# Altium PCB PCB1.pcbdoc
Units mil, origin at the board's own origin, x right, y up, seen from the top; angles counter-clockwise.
Board outline 3300 x 2640 mil, 2 copper layers (Top Layer, Bottom Layer), stack 62.2 mil thick; 4 components, 6 nets, 17 pads, 1 vias.
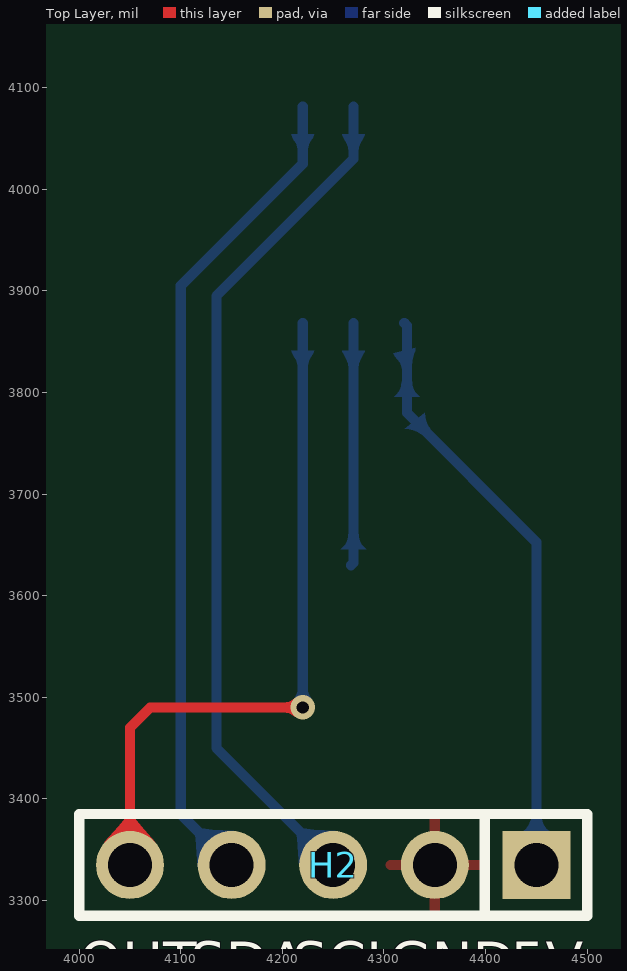
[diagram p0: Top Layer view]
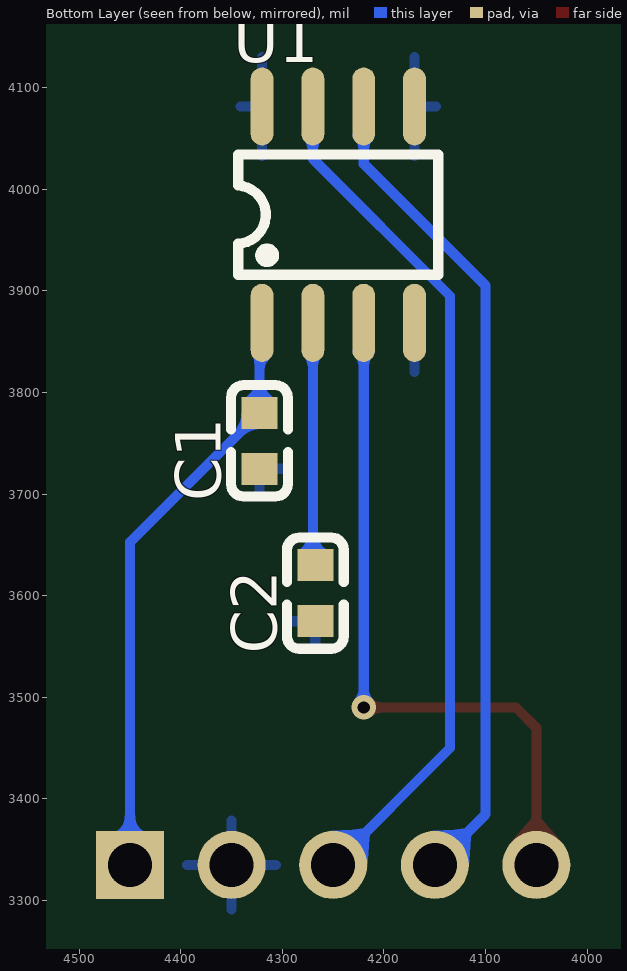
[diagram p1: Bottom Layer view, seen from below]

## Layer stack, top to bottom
Top Solder Mask Layer: solder mask 0.4, Dk 3.3
Top Layer: signal copper 1.4
Dielectric1: surface 59.4, FR4, Dk 4.5
Bottom Layer: signal copper 1.4
Bottom Solder Mask Layer: solder mask 0.4, Dk 3.3

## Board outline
6050,2750 2750,2750 2750,5390 6050,5390

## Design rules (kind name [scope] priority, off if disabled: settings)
BoardOutlineClearance copperThickness1oz [All] p0: genericclearance=10 ignorepadtopadclearanceinfootprint=FALSE except(0: Arc-SplitContinuation Track-SplitContinuation SMDPad-SplitContinuation THPad-SplitContinuation Via-SplitContinuation Fill-SplitContinuation Poly-SplitContinuation Region-SplitContinuation Text-SplitContinuation)
BoardOutlineClearance copperThickness2oz [All] p0: genericclearance=10 ignorepadtopadclearanceinfootprint=FALSE except(0: Arc-SplitContinuation Track-SplitContinuation SMDPad-SplitContinuation THPad-SplitContinuation Via-SplitContinuation Fill-SplitContinuation Poly-SplitContinuation Region-SplitContinuation Text-SplitContinuation)
BoardOutlineClearance otherClearance [All] p0: genericclearance=10 ignorepadtopadclearanceinfootprint=FALSE except(0: Arc-SplitContinuation Track-SplitContinuation SMDPad-SplitContinuation THPad-SplitContinuation Via-SplitContinuation Fill-SplitContinuation Poly-SplitContinuation Region-SplitContinuation Text-SplitContinuation)
Clearance copperThickness1oz [All] p1: gap=7 ignorepadtopadclearanceinfootprint=FALSE
Clearance copperThickness2oz [All] p1: gap=7 ignorepadtopadclearanceinfootprint=FALSE
Clearance otherClearance [All] p1: gap=7 ignorepadtopadclearanceinfootprint=FALSE
DiffPairsRouting differentialPair [All] p1: maxuncoupledlength=10 minlimit=6 maxlimit=Infinity mostfreqgap=6 toplayer_minwidth=5 toplayer_prefwidth=10 toplayer_maxwidth=100 bottomlayer_minwidth=5 bottomlayer_prefwidth=10 bottomlayer_maxwidth=100
PasteMaskExpansion pasteMaskExpansion [All] p1: expansion=0
PlaneConnect innerPlane [All] p1: planeconnectstyle=Relief reliefexpansion=20 reliefentries=4 reliefconductorwidth=10 reliefairgap=10
PolygonConnect copperRegion [All] p1: connectstyle=Relief reliefentries=4 reliefconductorwidth=10 polygonreliefangle="90 Angle" airgapwidth=10
RoutingVias viaSize [All] p1: viastyle="Through Hole" holewidth=12.0078 minholewidth=11.811 maxholewidth=248.0314 width=12.0078 minwidth=11.811 maxwidth=248.0314
SolderMaskExpansion solderMaskExpansion [IsVia] p1: useseparateexpansions=TRUE expansion=-1000 expansionbottom=-1000
SolderMaskExpansion solderMaskExpansion [All] p2: useseparateexpansions=TRUE expansion=2 expansionbottom=2
Width copperThickness1oz [All] p1: maxlimit=100 minlimit=5 preferedwidth=10
Width copperThickness2oz [All] p1: maxlimit=100 minlimit=8 preferedwidth=10

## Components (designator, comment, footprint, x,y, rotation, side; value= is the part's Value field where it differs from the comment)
C1 "100nF" C0603 4322.6,3752.4 r90 bottom
C2 "100nF" C0603 4267.6,3602.4 r90 bottom
H2 "" HDR-TH_5P-P2.54-V-M 4250,3335 r180 top
U1 "AS5600-ASOT" SOIC-8_L5.0-W4.0-P1.27-LS6.0-BL 4245,3975 r180 bottom

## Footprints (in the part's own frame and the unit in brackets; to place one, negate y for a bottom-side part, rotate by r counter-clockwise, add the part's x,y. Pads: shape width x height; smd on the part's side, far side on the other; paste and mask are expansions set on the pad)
C0603 [mil]
  rect 31.5x35.4 smd: 1(-27.5,0) 2(27.6,0)
  silkscreen extent -55,-28 55,28
HDR-TH_5P-P2.54-V-M [mil]
  rect 66.9x66.9 hole 43.3: 1(-200,0)
  round 66.9 hole 43.3: 2(-100,0) 3(0,0) 4(100,0) 5(200,0)
  silkscreen extent -250,-50 250,50
SOIC-8_L5.0-W4.0-P1.27-LS6.0-BL [mil]
  oval 22.4x76.8 smd: 1(-75,-106.5) 2(-25,-106.5) 3(25,-106.5) 4(75,-106.5) 5(75,106.5) 6(25,106.5) 7(-25,106.5) 8(-75,106.5)
  silkscreen extent -98,-59 98,59

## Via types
v1: diameter 24, hole 12, Top Layer to Bottom Layer, 1 vias

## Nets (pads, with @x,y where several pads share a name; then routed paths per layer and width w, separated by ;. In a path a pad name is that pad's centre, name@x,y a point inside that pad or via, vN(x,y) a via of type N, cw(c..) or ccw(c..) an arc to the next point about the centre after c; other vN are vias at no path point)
5V: C1.2 H2.1 U1.1 | length 587.3
  Bottom Layer w10: U1.1 4322.6,3865.9 C1.2 4450,3652.6 H2.1
$1N12: C2.2 U1.2 | length 239.5
  Bottom Layer w10: C2.2 4270,3632.4 U1.2
GND: C1.1 C2.1 H2.2 U1.4 U1.5 U1.8
OUT: H2.5 U1.3 | length 691.8
  Top Layer w10: H2.5 4050,3470 4070,3490 v1(4220,3490)
  Bottom Layer w10: v1(4220,3490) U1.3
SCL: H2.3 U1.7 | length 850.1
  Bottom Layer w10: H2.3 4135,3450 4135,3895 4270,4030 U1.7
SDA: H2.4 U1.6 | length 816.9
  Bottom Layer w10: H2.4 4100,3385 4100,3905 4220,4025 U1.6

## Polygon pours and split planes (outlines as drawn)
GND on Top Layer (solid, remove dead copper, pour order 0): 3065,5080 3065,3030 5485,3030 5485,5080
GND on Bottom Layer (solid, remove dead copper, pour order 2): 3000,5140 3000,3000 5800,3000 5800,5140

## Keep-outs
Board Outline Layer:
  lines w3.9: 3335.7,3972.3 ccw(c4241.2,3972.3) 5146.7,3972.3 ccw(c4241.2,3972.3) 3335.7,3972.3 ; 3764.9,3726.8 ccw(c3816.1,3726.8) 3867.3,3726.8 ccw(c3816.1,3726.8) 3764.9,3726.8 ; 4190,4463.2 ccw(c4241.2,4463.2) 4292.4,4463.2 ccw(c4241.2,4463.2) 4190,4463.2 ; 4615.2,3726.8 ccw(c4666.4,3726.8) 4717.6,3726.8 ccw(c4666.4,3726.8) 4615.2,3726.8

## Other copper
Top Layer:
  region net OUT: 4203.7,3485 4203.7,3495 4205.5,3495.3 4207.7,3496.3 4210.1,3497.5 4212.1,3499 4212.1,3481 4210.1,3482.5 4207.7,3483.7 4205.5,3484.7
  region net OUT: 4045,3380.6 4055,3380.6 4056.7,3378.4 4061.3,3373 4075.1,3357.1 4024.9,3357.1 4038.7,3373 4043.3,3378.4
Bottom Layer:
  region net 5V: 4445,3383.5 4455,3383.5 4455.3,3380 4456.3,3376.7 4457.8,3373.6 4459.9,3370.8 4462.5,3368.5 4437.5,3368.5 4440.1,3370.8 4442.2,3373.6 4443.7,3376.7 4444.7,3380 4445,3383.5
  region net 5V: 4345.6,3764.1 4336.5,3758.9 4332.9,3761.2 4329,3762.9 4324.9,3763.9 4320.6,3764.3 4340.3,3780 4340.6,3775.7 4341.6,3771.6 4343.3,3767.7 4345.6,3764.1
  region net 5V: 4317.6,3810.7 4327.6,3810.7 4327.9,3807.3 4328.8,3804 4330.4,3800.8 4332.5,3798.1 4335.1,3795.7 4310.1,3795.7 4312.6,3798.1 4314.7,3800.8 4316.3,3804 4317.2,3807.3 4317.6,3810.7
  region net 5V: 4327.6,3828.9 4317.6,3823.7 4317.5,3824.9 4317.2,3826 4316.4,3828.1 4315.1,3830.2 4313.6,3832.2 4310.8,3835.8 4309.7,3837.4 4309.1,3838.7 4330.9,3843.9 4331,3842.6 4330.7,3841.1 4329.5,3837.5 4328.2,3833.3 4327.7,3831.1
  region net $1N12: 4265,3660.7 4275,3660.7 4275.3,3657.3 4276.3,3654 4277.8,3650.8 4279.9,3648.1 4282.5,3645.7 4257.5,3645.7 4260.1,3648.1 4262.2,3650.8 4263.7,3654 4264.7,3657.3 4265,3660.7
  region net $1N12: 4275,3826.3 4265,3826.3 4264.7,3828.5 4264,3830.7 4263,3832.8 4261.9,3834.8 4259.8,3838.4 4259.1,3840 4258.8,3841.3 4281.2,3841.3 4280.9,3840 4280.2,3838.4 4278.1,3834.8 4277,3832.8 4276,3830.7 4275.3,3828.5
  region net SDA: 4114.2,3363.7 4121.3,3370.8 4124.1,3370.4 4131.1,3369.8 4152.1,3368.4 4116.6,3332.9 4115.2,3353.9 4114.6,3360.9
  region net SDA: 4225,4039.3 4215,4039.3 4214.7,4041.5 4214,4043.7 4213,4045.8 4211.9,4047.8 4209.8,4051.4 4209.1,4053 4208.8,4054.3 4231.2,4054.3 4230.9,4053 4230.2,4051.4 4228.1,4047.8 4227,4045.8 4226,4043.7 4225.3,4041.5
  region net SCL: 4275,4039.3 4265,4039.3 4264.7,4041.5 4264,4043.7 4263,4045.8 4261.9,4047.8 4259.8,4051.4 4259.1,4053 4258.8,4054.3 4281.2,4054.3 4280.9,4053 4280.2,4051.4 4278.1,4047.8 4277,4045.8 4276,4043.7 4275.3,4041.5
  region net SCL: 4214.2,3363.7 4221.3,3370.8 4224.1,3370.4 4231.1,3369.8 4252.1,3368.4 4216.6,3332.9 4215.2,3353.9 4214.6,3360.9
  region net OUT: 4225,3826.3 4215,3826.3 4214.7,3828.5 4214,3830.7 4213,3832.8 4211.9,3834.8 4209.8,3838.4 4209.1,3840 4208.8,3841.3 4231.2,3841.3 4230.9,3840 4230.2,3838.4 4228.1,3834.8 4227,3832.8 4226,3830.7 4225.3,3828.5
  region net OUT: 4215,3506.3 4225,3506.3 4225.3,3504.5 4226.3,3502.3 4227.5,3499.9 4229,3497.9 4211,3497.9 4212.5,3499.9 4213.7,3502.3 4214.7,3504.5

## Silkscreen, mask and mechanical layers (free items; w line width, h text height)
Top Silkscreen Layer:
  text "OUT" at 4000,3220 h39.4
  text "SDA" at 4110,3220 h39.4
  text "SCL" at 4210,3220 h39.4
  text "GND" at 4305,3220 h39.4
  text "5V" at 4425,3220 h39.4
